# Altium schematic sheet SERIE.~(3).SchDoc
size A4
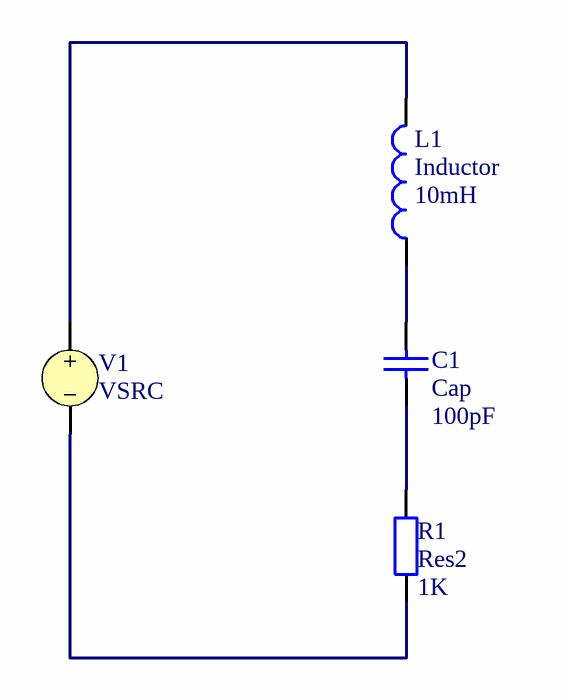
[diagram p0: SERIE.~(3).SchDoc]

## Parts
C1  Cap  value 100pF  [RAD-0.3]
L1  Inductor  value 10mH  [0402-A]
R1  Res2  value 1K  [AXIAL-0.4]
V1  VSRC

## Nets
NetC1_1: C1.1 L1.1
NetC1_2: C1.2 R1.2
NetL1_2: L1.2 V1.1
NetR1_1: R1.1 V1.2

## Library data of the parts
C1 = Cap: Capacitor
L1 = Inductor: Code_IEC: 1005
R1 = Res2: Resistor
V1 = VSRC: Voltage Source; Note: PCB Footprint - Not required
